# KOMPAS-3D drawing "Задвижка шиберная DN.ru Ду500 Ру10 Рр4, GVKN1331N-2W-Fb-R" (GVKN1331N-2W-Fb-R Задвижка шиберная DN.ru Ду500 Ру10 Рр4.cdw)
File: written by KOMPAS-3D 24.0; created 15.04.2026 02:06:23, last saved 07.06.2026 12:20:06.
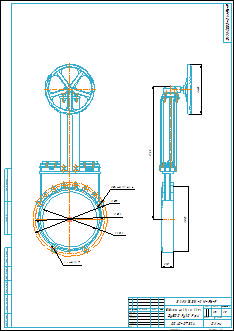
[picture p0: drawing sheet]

Document properties: Автор: DN.ru; Форматы листов документа: A2; Полное имя файла: GVKN1331N-2W-Fb-R Задвижка шиберная DN.ru Ду500 Ру10 Рр4.m3d; Масса: 192; Наименование: Задвижка шиберная DN.ru Ду500 Ру10 Рр4; Количество листов документа: 1; Примечание: D040-07324

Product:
- Part/product: Задвижка шиберная DN.ru Ду500 Ру10 Рр4  | designation GVKN1331N-2W-Fb-R
    Масса: 192
    Раздел спецификации: Прочие изделия
    Примечание: D040-07324

Views: Вид 1, Вид:1, Проекционный вид 2
Referenced files in C:\Работа\GVKN1331N-2W-Fb-R Задвижка шиберная DN.ru Ду400-600 Ру10\DN400\: GVKN1331N-2W-Fb-R Задвижка шиберная DN.ru Ду400 Ру10.m3d
Referenced files in E:\Работа\Зайцев\АУТСОРС\Даня\GVKN1331N-2W-Fb-R Задвижка шиберная DN.ru Ду400-600 Ру4-6\исходные материалы\DN500\DN500\: GVKN1331N-2W-Fb-R Задвижка шиберная DN.ru Ду500 Ру10 Рр4.m3d
Referenced files in C:\Program Files\ASCON\KOMPAS-3D v24\Templates\: Чертеж_DN.ru.cdt
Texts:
  GVKN1331N-2W-Fb-R
  Чертеж_DN.ru.cdt
  Задвижка шиберная DN.ru
  Ду500 Ру10 Рр4
  Задвижка шиберная DN.ru Ду500 Ру10 Рр4
  GVKN1331N-2W-Fb-R Задвижка шиберная DN.ru Ду500 Ру10 Рр4
Dimensions and other numbers on the sheet: 0; 3; 2; 4; 500; 670; 620; 16 отв.; 24; 2 отв.; 27; 1; 1200; 582; 105; 450; 1:5; 192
